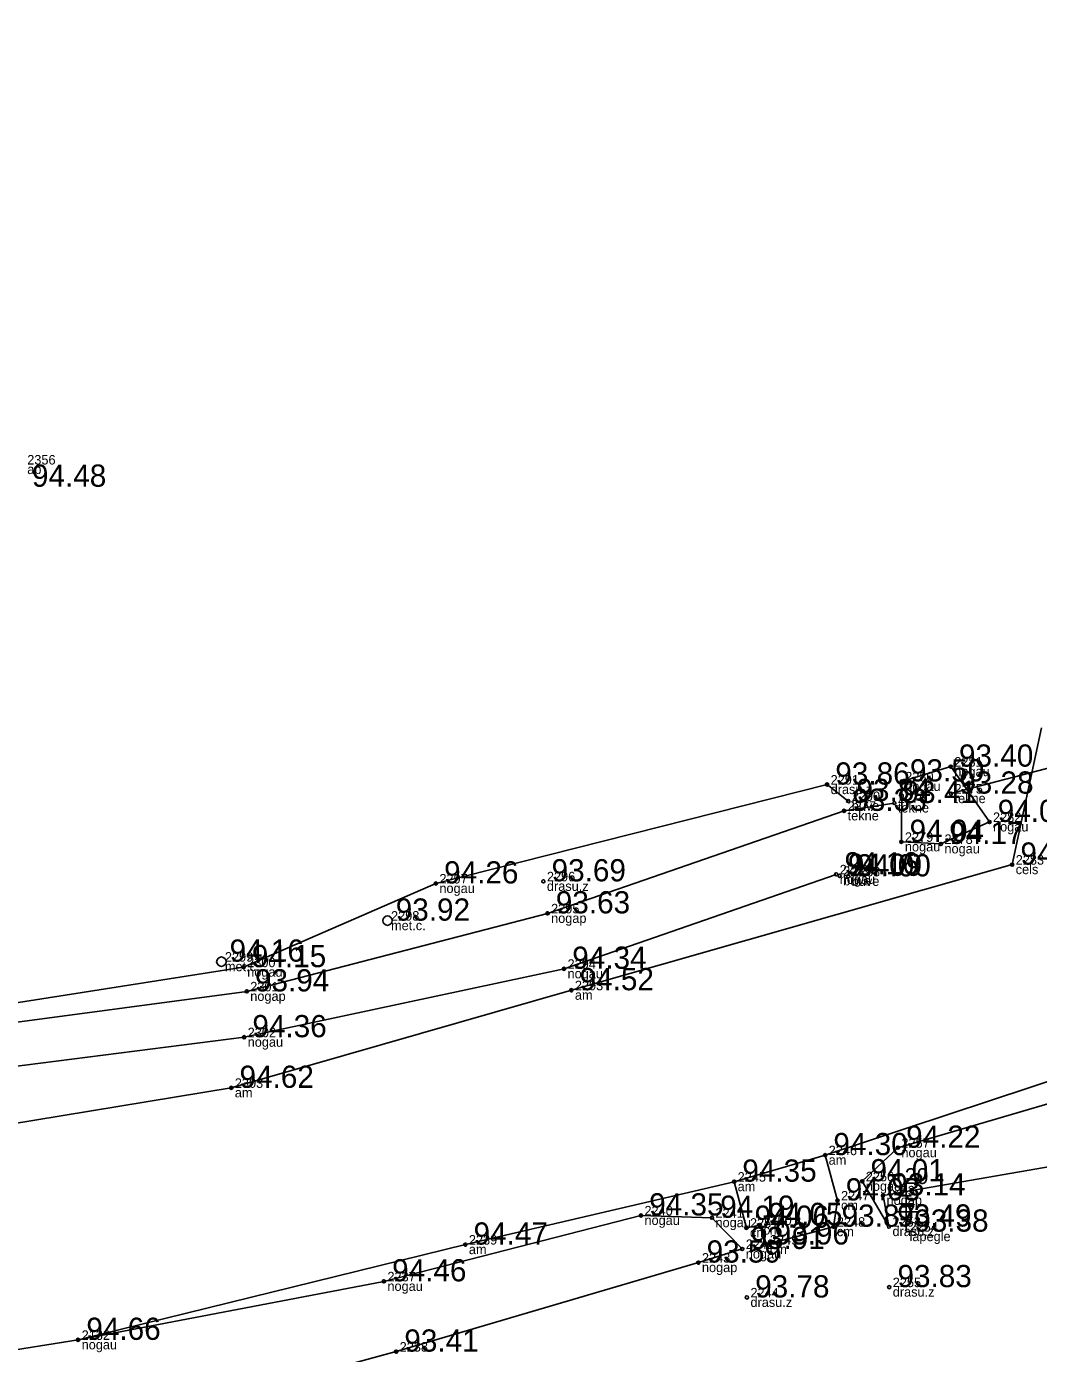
# Model space of a CAD drawing. Extents: x 614911 to 615803, y 262110 to 264311.
# Drawn here: x 615657.76 to 615689.65, y 263599.1 to 263640.94 of the extents above; entities that cross this region are included whole.
import ezdxf

# ---------------------------------------------------------------- set-up
doc = ezdxf.new("R2010")
doc.units = 0
for name, color, linetype in [('Level 1', 7, 'Continuous'), ('Level 11', 7, 'Continuous'), ('Level 14', 7, 'Continuous'), ('Level 31', 7, 'Continuous'), ('Level 37', 7, 'Continuous'), ('Level 53', 7, 'Continuous'), ('Level 54', 7, 'Continuous'), ('Level 57', 7, 'Continuous'), ('Level 58', 7, 'Continuous')]:
    doc.layers.add(name, color=color, linetype=linetype)

msp = doc.modelspace()

# ---------------------------------------------------------------- linework, layer by layer
at = {"layer": 'Level 1'}
for p, q in [((615685.474, 263604.444), (615685.474, 263602.944)), ((615685.31, 263604.068), (615685.638, 263604.068)), ((615685.118, 263603.568), (615685.83, 263603.568)), ((615685.244, 263603.818), (615685.704, 263603.818)), ((615685.31, 263603.322), (615685.638, 263603.322)), ((615685.474, 263602.944), (615685.674, 263602.944))]:
    msp.add_line(p, q, dxfattribs=at)
at = {"layer": 'Level 11'}
for p, q in [((615692.765, 263618.297), (615686.892, 263616.753)), ((615683.523, 263616.209), (615685.105, 263616.457))]:
    msp.add_line(p, q, dxfattribs=at)
at = {"layer": 'Level 14'}
for centre in [(615669.133, 263612.748), (615663.897, 263611.455)]:
    msp.add_circle(centre, 0.148, dxfattribs=at)
at = {"layer": 'Level 31'}
for points in [[(615635.404, 263622.144), (615634.552, 263621.153), (615634.659, 263617.543), (615635.629, 263614.969), (615636.312, 263613.055), (615636.853, 263611.434), (615639.652, 263609.969), (615644.526, 263608.765), (615649.756, 263607.226), (615653.25, 263607.628), (615664.615, 263609.073), (615674.696, 263611.23), (615683.275, 263614.206)], [(615683.652, 263616.52), (615682.987, 263617.038), (615670.657, 263613.92), (615664.599, 263611.281), (615654.418, 263609.687), (615650.647, 263609.338), (615644.124, 263610.911), (615640.372, 263611.576), (615639.339, 263612.12), (615638.498, 263613.119), (615637.649, 263615.194), (615636.891, 263617.877), (615636.439, 263621.377), (615635.404, 263622.144)], [(615644.233, 263609.989), (615650.357, 263608.527), (615653.284, 263608.995), (615664.696, 263610.518), (615674.177, 263612.977), (615683.523, 263616.209)], [(615696.712, 263608.608), (615690.734, 263607.202), (615685.217, 263605.589), (615684.095, 263604.531), (615684.936, 263603.104)], [(615684.936, 263603.104), (615684.75, 263604.086), (615692.079, 263605.35), (615697.099, 263607.295)], [(615680.313, 263602.397), (615679.358, 263603.382), (615677.12, 263603.454), (615669.019, 263601.376), (615659.382, 263599.532), (615651.478, 263598.277), (615647.143, 263595.409), (615645.002, 263589.292)], [(615669.404, 263599.161), (615678.931, 263601.968), (615680.313, 263602.397)]]:
    msp.add_lwpolyline(points, dxfattribs=at)
msp.add_lwpolyline([(615685.338, 263617.137), (615685.328, 263615.232), (615686.574, 263615.167), (615688.105, 263615.86), (615686.884, 263617.603)], close=True, dxfattribs=at)
at = {"layer": 'Level 37'}
for points in [[(615689.749, 263618.823), (615688.82, 263614.514), (615674.927, 263610.554), (615664.21, 263607.477), (615651.825, 263605.439), (615644.676, 263607.111), (615640.138, 263609.414), (615639.508, 263609.578), (615637.855, 263610.48), (615636.285, 263611.639), (615636.027, 263611.907), (615634.803, 263613.377), (615634.369, 263614.767), (615633.519, 263617.584), (615633.336, 263625.21), (615633.344, 263651.772), (615633.393, 263671.43), (615633.395, 263690.2), (615635.468, 263691.528), (615641.886, 263693.128), (615652.363, 263692.83)], [(615622.954, 263597.67), (615628.907, 263597.13), (615631.65, 263596.73), (615651.478, 263598.277), (615659.382, 263599.532), (615671.586, 263602.535), (615680.056, 263604.519), (615682.925, 263605.355), (615694.583, 263609.208), (615696.467, 263609.569)], [(615680.056, 263604.519), (615680.445, 263603.066), (615680.868, 263603.153), (615681.073, 263602.538), (615683.184, 263603.099), (615683.315, 263603.926), (615682.925, 263605.355)], [(615645.002, 263589.292), (615647.359, 263589.675), (615649.972, 263592.807), (615660.074, 263596.62), (615669.404, 263599.161)]]:
    msp.add_lwpolyline(points, dxfattribs=at)
at = {"layer": 'Level 57'}
for centre in [(615686.884, 263617.603), (615682.987, 263617.038), (615685.338, 263617.137), (615683.652, 263616.52), (615685.105, 263616.457), (615686.892, 263616.753), (615683.523, 263616.209), (615688.105, 263615.86), (615685.328, 263615.232), (615686.574, 263615.167), (615688.82, 263614.514), (615670.657, 263613.92), (615674.045, 263613.987), (615683.275, 263614.206), (615683.382, 263614.16), (615683.653, 263614.143), (615674.177, 263612.977), (615664.599, 263611.281), (615674.696, 263611.23), (615674.927, 263610.554), (615664.696, 263610.518), (615664.615, 263609.073), (615664.21, 263607.477), (615685.217, 263605.589), (615682.925, 263605.355), (615680.056, 263604.519), (615684.095, 263604.531), (615683.315, 263603.926), (615684.75, 263604.086), (615677.12, 263603.454), (615679.358, 263603.382), (615680.445, 263603.066), (615680.868, 263603.153), (615683.184, 263603.099), (615684.936, 263603.104), (615671.586, 263602.535), (615680.313, 263602.397), (615681.073, 263602.538), (615678.931, 263601.968), (615669.019, 263601.376), (615684.945, 263601.194), (615680.46, 263600.869), (615659.382, 263599.532), (615669.404, 263599.161)]:
    msp.add_circle(centre, 0.05, dxfattribs=at)
at = {"layer": 'Level 58'}
for centre in [(615686.884, 263617.603), (615682.987, 263617.038), (615685.338, 263617.137), (615683.652, 263616.52), (615685.105, 263616.457), (615686.892, 263616.753), (615683.523, 263616.209), (615688.105, 263615.86), (615685.328, 263615.232), (615686.574, 263615.167), (615688.82, 263614.514), (615670.657, 263613.92), (615674.045, 263613.987), (615683.275, 263614.206), (615683.382, 263614.16), (615683.653, 263614.143), (615674.177, 263612.977), (615664.599, 263611.281), (615674.696, 263611.23), (615674.927, 263610.554), (615664.696, 263610.518), (615664.615, 263609.073), (615664.21, 263607.477), (615685.217, 263605.589), (615682.925, 263605.355), (615680.056, 263604.519), (615684.095, 263604.531), (615683.315, 263603.926), (615684.75, 263604.086), (615677.12, 263603.454), (615679.358, 263603.382), (615680.445, 263603.066), (615680.868, 263603.153), (615683.184, 263603.099), (615684.936, 263603.104), (615671.586, 263602.535), (615680.313, 263602.397), (615681.073, 263602.538), (615678.931, 263601.968), (615669.019, 263601.376), (615684.945, 263601.194), (615680.46, 263600.869), (615659.382, 263599.532), (615669.404, 263599.161)]:
    msp.add_circle(centre, 0.05, dxfattribs=at)

# ---------------------------------------------------------------- texts
at = {"layer": 'Level 1'}
msp.add_text(' 20', height=0.5, dxfattribs=at).set_placement((615685.249, 263604.444))
at = {"layer": 'Level 53'}
for s, p in [(' ap', (615657.668, 263626.828)), (' nogau', (615686.884, 263617.303)), (' drasu.z', (615682.987, 263616.738)), (' nogau', (615685.338, 263616.837)), (' buve', (615683.652, 263616.22)), (' tekne', (615685.105, 263616.157)), (' tekne', (615686.892, 263616.453)), (' tekne', (615683.523, 263615.909)), (' nogau', (615688.105, 263615.56)), (' nogau', (615685.328, 263614.932)), (' nogau', (615686.574, 263614.867)), (' cels', (615688.82, 263614.214)), (' drasu.z', (615674.045, 263613.687)), (' nogau', (615683.275, 263613.906)), (' buve', (615683.382, 263613.86)), (' buve', (615683.653, 263613.843)), (' nogau', (615670.657, 263613.62)), (' met.c.', (615669.133, 263612.448)), (' nogap', (615674.177, 263612.677)), (' met.c.', (615663.897, 263611.155)), (' nogau', (615664.599, 263610.981)), (' nogau', (615674.696, 263610.93)), (' nogap', (615664.696, 263610.218)), (' am', (615674.927, 263610.254)), (' nogau', (615664.615, 263608.773)), (' am', (615664.21, 263607.177)), (' am', (615682.925, 263605.055)), (' nogau', (615685.217, 263605.289)), (' am', (615680.056, 263604.219)), (' nogau', (615684.095, 263604.231)), (' nogap', (615684.75, 263603.786)), (' cm', (615683.315, 263603.626)), (' nogau', (615677.12, 263603.154)), (' nogau', (615679.358, 263603.082)), (' cm', (615680.868, 263602.853)), (' drasu.z', (615684.936, 263602.804)), (' cm', (615680.445, 263602.766)), (' cm', (615683.184, 263602.799)), (' lapegle', (615685.474, 263602.644)), (' am', (615671.586, 263602.235)), (' nogau', (615680.313, 263602.097)), (' cm', (615681.073, 263602.238)), (' nogap', (615678.931, 263601.668)), (' nogau', (615669.019, 263601.076)), (' drasu.z', (615684.945, 263600.894)), (' drasu.z', (615680.46, 263600.569)), (' nogau', (615659.382, 263599.232))]:
    msp.add_text(s, height=0.3, dxfattribs=at).set_placement(p)
at = {"layer": 'Level 54'}
for s, p in [(' 2356', (615657.668, 263627.128)), (' 2281', (615686.884, 263617.603)), (' 2291', (615682.987, 263617.038)), (' 2280', (615685.338, 263617.137)), (' 2275', (615686.892, 263616.753)), (' 2277', (615683.523, 263616.209)), (' 2290', (615683.652, 263616.52)), (' 2276', (615685.105, 263616.457)), (' 2282', (615688.105, 263615.86)), (' 2279', (615685.328, 263615.232)), (' 2278', (615686.574, 263615.167)), (' 2283', (615688.82, 263614.514)), (' 2292', (615683.275, 263614.206)), (' 2289', (615683.382, 263614.16)), (' 2288', (615683.653, 263614.143)), (' 2297', (615670.657, 263613.92)), (' 2296', (615674.045, 263613.987)), (' 2295', (615674.177, 263612.977)), (' 2298', (615669.133, 263612.748)), (' 2299', (615663.897, 263611.455)), (' 2300', (615664.599, 263611.281)), (' 2294', (615674.696, 263611.23)), (' 2301', (615664.696, 263610.518)), (' 2293', (615674.927, 263610.554)), (' 2302', (615664.615, 263609.073)), (' 2303', (615664.21, 263607.477)), (' 2246', (615682.925, 263605.355)), (' 2257', (615685.217, 263605.589)), (' 2245', (615680.056, 263604.519)), (' 2256', (615684.095, 263604.531)), (' 2253', (615684.75, 263604.086)), (' 2247', (615683.315, 263603.926)), (' 2240', (615677.12, 263603.454)), (' 2241', (615679.358, 263603.382)), (' 2250', (615680.868, 263603.153)), (' 2251', (615680.445, 263603.066)), (' 2248', (615683.184, 263603.099)), (' 2252', (615684.936, 263603.104)), (' 2254', (615685.474, 263602.944)), (' 2239', (615671.586, 263602.535)), (' 2242', (615680.313, 263602.397)), (' 2249', (615681.073, 263602.538)), (' 2243', (615678.931, 263601.968)), (' 2237', (615669.019, 263601.376)), (' 2255', (615684.945, 263601.194)), (' 2244', (615680.46, 263600.869)), (' 2132', (615659.382, 263599.532)), (' 2238', (615669.404, 263599.161))]:
    msp.add_text(s, height=0.3, dxfattribs=at).set_placement(p)
at = {"layer": 'Level 58'}
for s, p in [(' 94.48', (615657.668, 263626.428)), (' 93.40', (615686.884, 263617.603)), (' 93.86', (615682.987, 263617.038)), (' 93.50', (615685.338, 263617.137)), (' 93.28', (615686.892, 263616.753)), (' 93.33', (615683.523, 263616.209)), (' 93.84', (615683.652, 263616.52)), (' 93.41', (615685.105, 263616.457)), (' 94.01', (615688.105, 263615.86)), (' 94.04', (615685.328, 263615.232)), (' 94.17', (615686.574, 263615.167)), (' 94.15', (615688.82, 263614.514)), (' 94.16', (615683.275, 263614.206)), (' 94.09', (615683.382, 263614.16)), (' 94.00', (615683.653, 263614.143)), (' 94.26', (615670.657, 263613.92)), (' 93.69', (615674.045, 263613.987)), (' 93.63', (615674.177, 263612.977)), (' 93.92', (615669.133, 263612.748)), (' 94.16', (615663.897, 263611.455)), (' 94.15', (615664.599, 263611.281)), (' 94.34', (615674.696, 263611.23)), (' 93.94', (615664.696, 263610.518)), (' 94.52', (615674.927, 263610.554)), (' 94.36', (615664.615, 263609.073)), (' 94.62', (615664.21, 263607.477)), (' 94.30', (615682.925, 263605.355)), (' 94.22', (615685.217, 263605.589)), (' 94.35', (615680.056, 263604.519)), (' 94.01', (615684.095, 263604.531)), (' 93.14', (615684.75, 263604.086)), (' 94.03', (615683.315, 263603.926)), (' 94.35', (615677.12, 263603.454)), (' 94.19', (615679.358, 263603.382)), (' 94.06', (615680.445, 263603.066)), (' 94.05', (615680.868, 263603.153)), (' 93.87', (615683.184, 263603.099)), (' 93.49', (615684.936, 263603.104)), (' 93.38', (615685.474, 263602.944)), (' 94.47', (615671.586, 263602.535)), (' 93.91', (615680.313, 263602.397)), (' 93.96', (615681.073, 263602.538)), (' 93.59', (615678.931, 263601.968)), (' 94.46', (615669.019, 263601.376)), (' 93.83', (615684.945, 263601.194)), (' 93.78', (615680.46, 263600.869)), (' 94.66', (615659.382, 263599.532)), (' 93.41', (615669.404, 263599.161))]:
    msp.add_text(s, height=0.7, dxfattribs=at).set_placement(p)

doc.saveas('drawing.dxf')
